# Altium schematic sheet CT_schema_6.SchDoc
size 368 x 245 mm
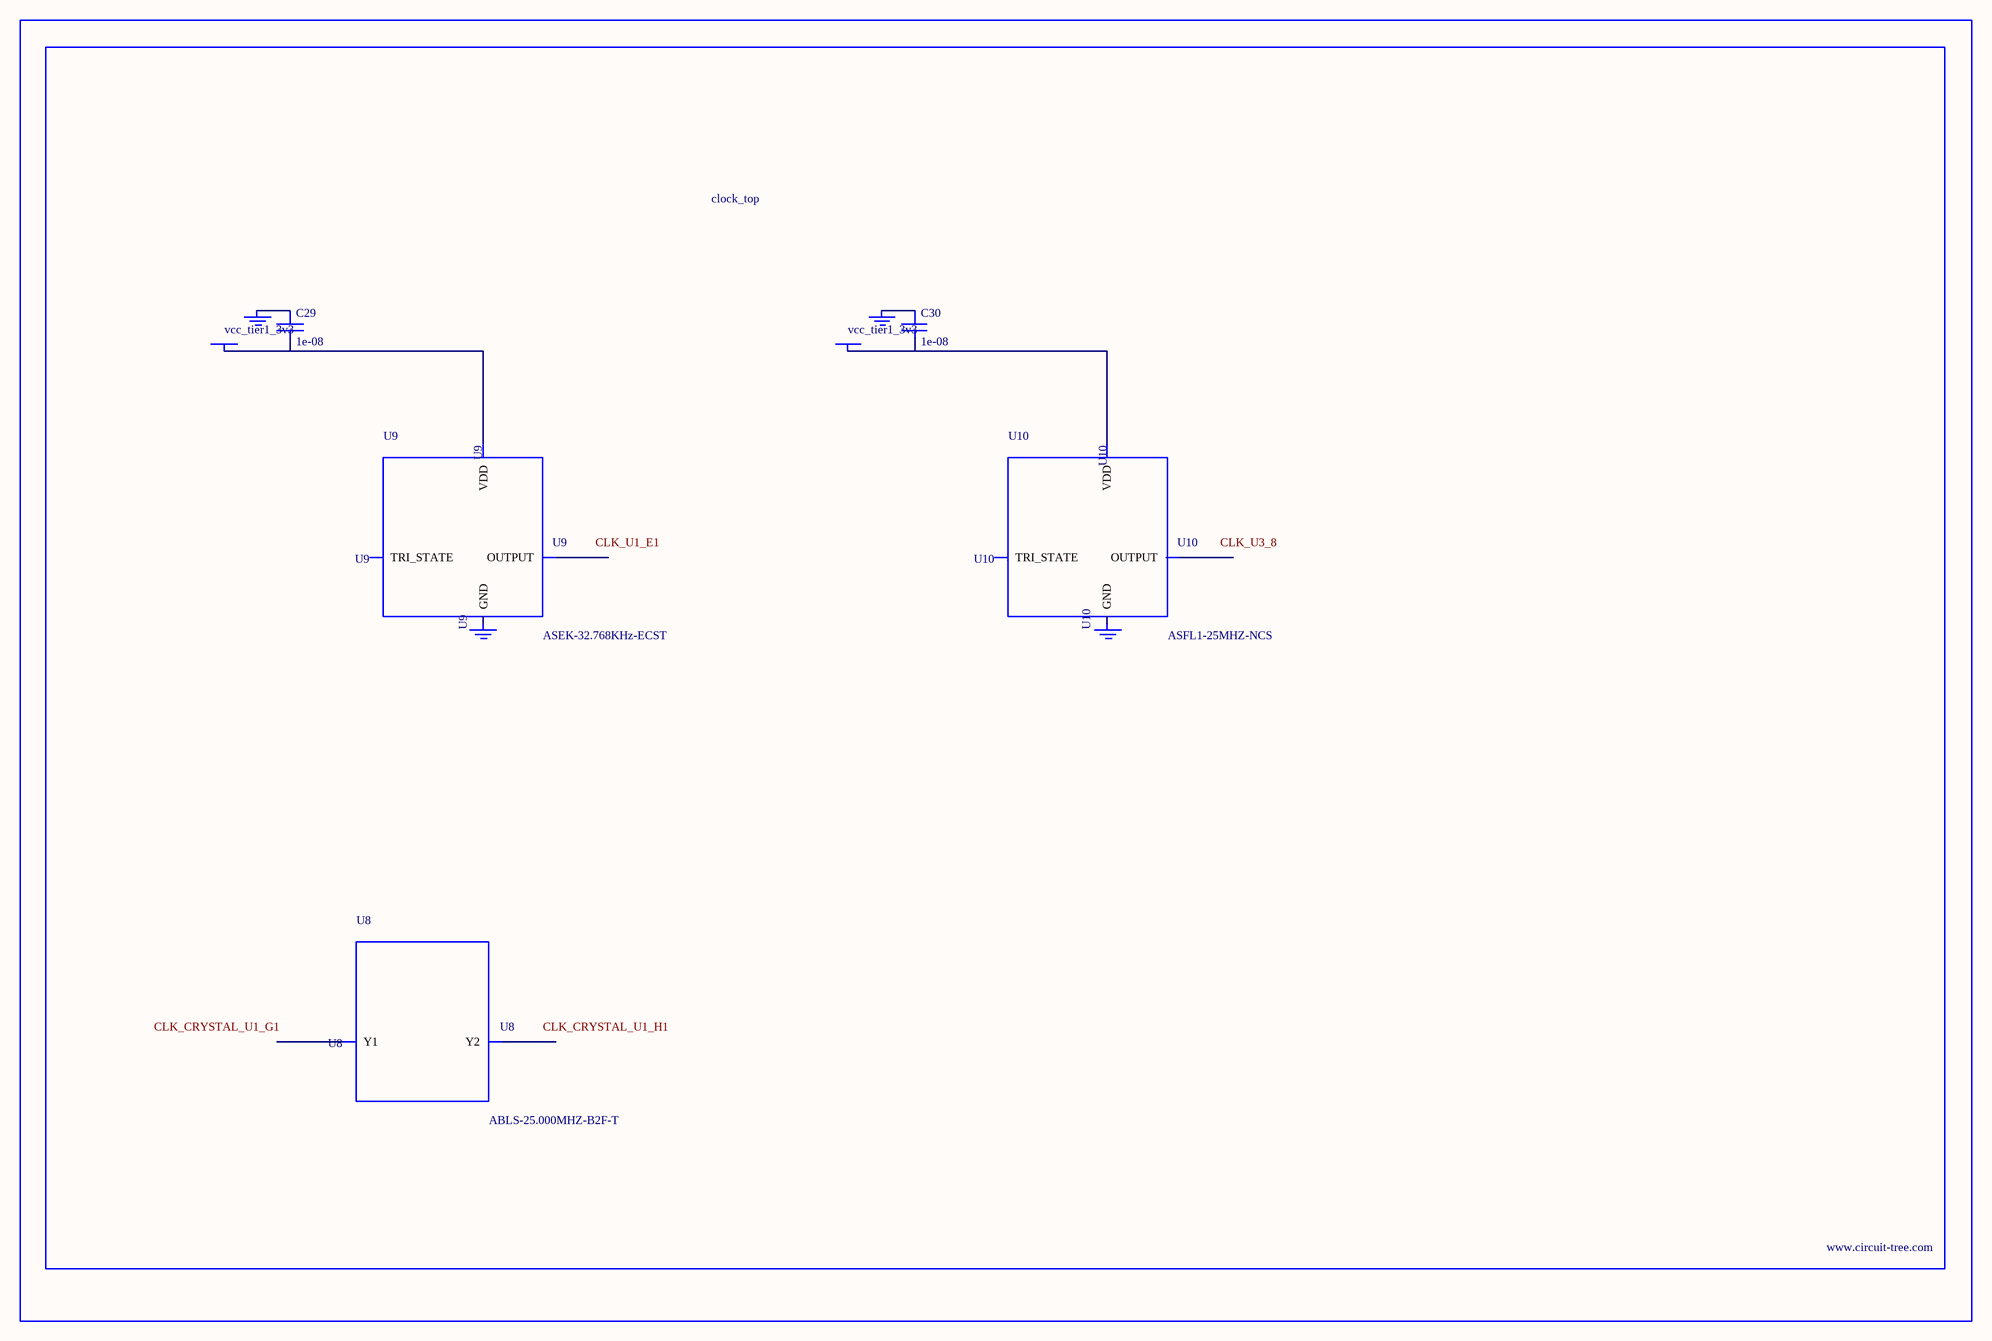
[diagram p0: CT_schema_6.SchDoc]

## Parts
BORDER5  (no value)
C29  1e-08  [C0402]
C30  1e-08  [C0402]
GND_INSTANCE_5_0  (no value)
GND_INSTANCE_5_1  (no value)
GND_INSTANCE_5_2  (no value)
GND_INSTANCE_5_3  (no value)
POWER_INSTANCE_5_0  vcc_tier1_3v3
POWER_INSTANCE_5_1  vcc_tier1_3v3
U8  ABLS-25.000MHZ-B2F-T  [ABLS-25.000MHZ-B2F-T]
U9  ASEK-32.768KHz-ECST  [ASEK]
U10  ASFL1-25MHZ-NCS  [ASFL1]

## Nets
NetC29_1: C29.1 GND_INSTANCE_5_0.0(GND)
NetC29_2: C29.2 POWER_INSTANCE_5_0.0(PWR) U9.4(VDD)
NetC30_1: C30.1 GND_INSTANCE_5_2.0(GND)
NetC30_2: C30.2 POWER_INSTANCE_5_1.0(PWR) U10.4(VDD)

Not connected (* = marked no-connect by the designer): GND_INSTANCE_5_1 0(GND); GND_INSTANCE_5_3 0(GND); U8 1(Y1) 2(Y2); U9 1(TRI_STATE) 2(GND) 3(OUTPUT); U10 1(TRI_STATE) 2(GND) 3(OUTPUT)

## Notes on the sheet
- Labels drawn without touching a wire or pin: CLK_CRYSTAL_U1_G1, CLK_CRYSTAL_U1_H1, CLK_U1_E1, CLK_U3_8

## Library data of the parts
BORDER5 = BORDER_PAGE5
C29 C30 = C0402C103K3RAC
GND_INSTANCE_5_0-GND_INSTANCE_5_3 = GND
POWER_INSTANCE_5_0 POWER_INSTANCE_5_1 = PWR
